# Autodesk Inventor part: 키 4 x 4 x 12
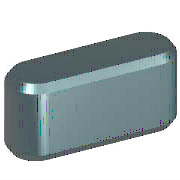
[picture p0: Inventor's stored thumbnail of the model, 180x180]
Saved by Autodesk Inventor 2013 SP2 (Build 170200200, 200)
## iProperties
IsCustomPart: 1
Created: 2012-02
Part Number: 키 4 x 4 x 12
Material: 강철, 연강
Description: 키 및 해당 키홈
Document SubType Name: Modeling
Standard: KS B 1311
Designer: mduedu
Standards Organization: KS
Language: ko-KR
Size Designation: 4 x 4 x 12
Categories: <MemberInstance><Categories><Category DisplayName="샤프트 부품" InternalName="7f7aeb1f-a693-4053-b835-cee3144e0d98" Mnemonic="SHFT"><Category DisplayName="키" Interna
Density: 7.86 g/cm^3
Mass: 1.38739 g
Surface Area: 1.94869 cm^2
Volume: 0.176513 cm^3
Author: mduedu
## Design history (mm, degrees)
workplane "Work Plane1"
workplane "Work Plane2"
sketch "스케치1"
  geometry: L1 (2, 2)-(10, 2); L2 (10, -2)-(2, -2); L3 (0, 9.4)-(0, -7.4) reference; L4 (-5, 0)-(30, 0) reference; L5 (12, 0)-(12, 7); A1 r 2 centre (2, 0) between (2, 2) and (2, -2); A2 r 2 centre (10, 0) between (10, -2) and (10, 2)
  constraints: 6 end point, 5 point on circle, 4 tangent, 3 point on line, 2 centre point, 1 horizontal, 1 parallel, 1 perpendicular
  dimensions: "d0" = 2 radius of A1 (= 0.5 x PB); "d13" = 2 radius of A2 (= 0.5 x PB); "d14" = 12 distance between parallel lines of L5 L3 (= NLG)
extrude "본체1" new body sketch "스케치1" taper "d3" = 0 deg; stored distance "d4" = 10
workplane "Work Plane3"
body "Solid1"
chamfer "모따기1" distance "d8" = 0.25 (= PHH); stored, may be unused: second distance "d9" = 0.25 (= PHH), angle "d15" = 45 deg
other parameters: "d1" = -2.5 (= -PNT), "d2" = 1.5 (= PH - PNT), "NLG" = 12 [user parameter; used in 3 equation terms], "PB" = 4 [user parameter; used in 2 equation terms], "PNT" = 2.5 [user parameter; used in 2 equation terms], "PH" = 4 [user parameter; used in 1 equation term], "PHH" = 0.25 [user parameter; used in 2 equation terms], "d10" = 0, "d16" = 0, "d17" = 0, "d18" = 0, "PLB2" = 12 (= NLG) [user parameter], "WDMAX" = 12 [user parameter], "PLB1" = 12 (= NLG) [user parameter], "RR" = 0.08 [user parameter], "PUEB" = 1.8 [user parameter]
